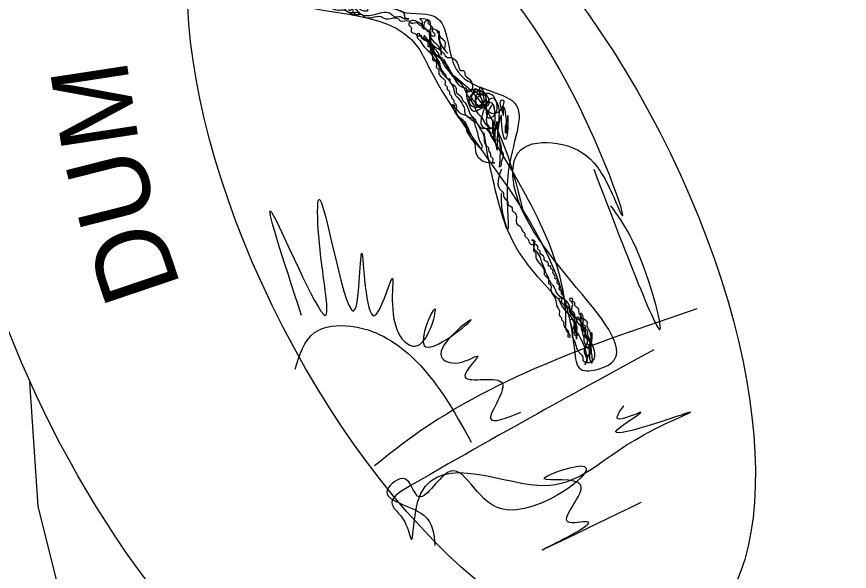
# Model space of a CAD drawing. Extents: x 160093 to 164626, y 177093 to 182727.
# Drawn here: x 162728.73 to 162751.34, y 178249.07 to 178264.12 of the extents above; entities that cross this region are included whole.
import ezdxf

# ---------------------------------------------------------------- set-up
doc = ezdxf.new("R2010")
doc.units = 0
doc.layers.add('Level 38', color=7, linetype='Continuous')
doc.layers.add('Level 40', color=7, linetype='Continuous')

msp = doc.modelspace()

# ---------------------------------------------------------------- linework, layer by layer
at = {"layer": 'Level 38'}
msp.add_lwpolyline([(162729.077, 178254.203), (162729.302, 178250.833), (162730.119, 178247.567), (162730.772, 178245.77), (162730.772, 178245.443)], dxfattribs=at)
for centre, major_axis, ratio in [((162741.339, 178258.256), (9.304, -16.888), 0.662421), ((162741.077, 178258.344), (5.775, -11.2), 0.456916)]:
    msp.add_ellipse(centre, major_axis=major_axis, ratio=ratio, dxfattribs=at)
for points in [[(162733.843, 178267.269), (162735.477, 178264.761), (162739.619, 178263.302), (162739.91, 178262.777), (162743.877, 178255.077), (162744.052, 178254.552), (162744.519, 178254.552), (162742.244, 178259.511), (162742.419, 178260.502), (162743.41, 178260.677), (162744.402, 178260.152), (162745.044, 178258.986), (162739.619, 178266.277), (162739.093, 178266.277), (162738.102, 178268.552), (162736.818, 178267.736), (162738.102, 178265.927), (162736.935, 178264.936), (162736.468, 178264.936), (162735.01, 178265.752), (162733.843, 178267.911)], [(162738.802, 178265.286), (162739.093, 178264.294), (162740.085, 178264.119), (162740.727, 178262.602), (162742.244, 178261.786), (162742.069, 178259.802), (162742.069, 178258.344), (162741.602, 178259.977), (162741.427, 178260.969)], [(162737.052, 178264.352), (162737.168, 178264.352), (162737.227, 178264.352), (162737.46, 178264.294), (162737.635, 178264.294), (162737.752, 178264.236), (162737.985, 178264.236), (162738.102, 178264.177), (162738.452, 178264.177), (162738.918, 178264.177), (162738.977, 178264.119), (162739.152, 178264.119), (162739.268, 178264.061), (162739.385, 178264.061), (162739.327, 178264.061), (162739.268, 178264.119), (162739.268, 178264.177), (162739.093, 178264.294), (162738.918, 178264.352), (162738.743, 178264.469), (162738.568, 178264.527), (162738.102, 178264.644), (162738.16, 178264.644), (162738.393, 178264.411), (162738.452, 178264.411), (162738.452, 178264.469), (162738.51, 178264.644), (162738.743, 178264.411), (162738.685, 178264.469), (162738.685, 178264.586), (162738.627, 178264.586), (162738.627, 178264.527), (162738.627, 178264.411), (162738.277, 178264.644), (162738.102, 178264.644), (162737.927, 178264.586), (162737.927, 178264.527), (162737.985, 178264.469), (162738.16, 178264.352), (162738.218, 178264.352), (162738.16, 178264.411), (162738.16, 178264.469), (162738.043, 178264.586), (162737.985, 178264.586), (162737.927, 178264.527), (162737.985, 178264.411), (162738.102, 178264.294), (162738.277, 178264.294), (162738.218, 178264.352), (162737.868, 178264.352), (162737.868, 178264.236), (162738.043, 178264.177), (162737.868, 178264.352), (162737.752, 178264.352), (162737.752, 178264.294), (162737.81, 178264.294), (162737.81, 178264.411), (162737.752, 178264.469), (162737.693, 178264.469), (162737.635, 178264.527), (162737.635, 178264.469), (162737.577, 178264.469), (162737.635, 178264.411), (162737.635, 178264.352), (162737.752, 178264.236), (162737.868, 178264.177), (162737.985, 178264.177), (162738.102, 178264.177), (162738.16, 178264.119), (162738.627, 178264.119), (162738.743, 178264.061), (162739.093, 178264.061), (162739.152, 178264.002), (162739.385, 178264.002), (162739.444, 178263.944), (162739.619, 178263.944), (162739.677, 178263.886), (162739.735, 178263.886), (162739.735, 178263.827), (162739.794, 178263.827), (162739.91, 178263.711), (162739.969, 178263.711), (162739.969, 178263.652), (162740.027, 178263.594), (162740.085, 178263.594), (162740.085, 178263.652), (162740.027, 178263.711), (162740.027, 178263.827), (162739.969, 178263.886), (162739.969, 178263.944), (162739.735, 178264.061), (162739.677, 178264.061), (162739.735, 178264.002), (162739.735, 178263.886), (162739.852, 178263.769), (162739.969, 178263.769), (162739.969, 178263.886)], [(162739.969, 178263.886), (162739.91, 178263.944), (162739.91, 178264.002), (162739.852, 178264.002), (162739.794, 178263.944), (162739.794, 178263.769), (162739.794, 178263.827), (162739.677, 178263.944), (162739.56, 178264.002), (162739.444, 178264.002), (162739.385, 178263.944), (162739.385, 178263.886), (162739.444, 178263.827), (162739.444, 178263.711), (162739.56, 178263.652), (162739.619, 178263.594), (162739.677, 178263.594), (162739.735, 178263.536), (162739.969, 178263.419), (162740.027, 178263.361), (162740.319, 178263.127), (162740.435, 178263.011), (162740.494, 178263.011), (162740.727, 178262.777), (162740.785, 178262.661), (162740.844, 178262.661), (162740.902, 178262.602), (162740.902, 178262.544), (162741.019, 178262.427), (162741.019, 178262.077), (162740.96, 178262.077), (162740.96, 178262.136), (162740.844, 178262.194), (162740.669, 178262.369), (162740.435, 178262.719), (162740.377, 178262.836), (162740.26, 178262.952), (162740.144, 178263.186), (162740.085, 178263.244), (162740.027, 178263.361), (162739.969, 178263.419), (162739.969, 178263.652), (162739.969, 178263.594), (162740.027, 178263.477), (162740.26, 178263.127), (162740.26, 178263.069), (162740.26, 178263.244), (162740.202, 178263.652), (162740.202, 178263.711), (162740.144, 178263.711), (162740.202, 178263.652), (162740.202, 178263.594), (162740.26, 178263.361), (162740.377, 178263.186), (162740.435, 178263.127), (162740.377, 178263.186), (162740.377, 178263.419), (162740.26, 178263.536), (162740.202, 178263.652), (162740.085, 178263.769), (162739.969, 178263.769), (162739.969, 178263.477), (162740.027, 178263.186), (162740.202, 178262.836), (162740.144, 178262.894), (162740.144, 178263.011), (162740.027, 178263.244), (162739.969, 178263.419), (162739.91, 178263.477), (162739.852, 178263.536), (162739.91, 178263.477), (162740.027, 178263.302), (162740.085, 178263.127), (162740.26, 178263.011), (162740.319, 178262.952), (162740.61, 178262.486), (162740.785, 178262.311), (162740.902, 178262.136), (162741.019, 178261.902), (162741.135, 178261.727), (162741.252, 178261.494), (162741.369, 178261.377), (162741.427, 178261.261), (162741.544, 178261.086), (162741.602, 178260.969), (162741.66, 178260.969), (162741.66, 178261.027), (162741.719, 178261.261), (162741.719, 178261.436), (162741.602, 178261.786), (162741.544, 178261.786), (162741.485, 178261.727), (162741.369, 178261.436), (162741.369, 178261.144), (162741.485, 178261.086), (162741.602, 178261.086), (162741.719, 178261.202)], [(162741.835, 178260.036), (162741.894, 178260.094), (162741.894, 178260.152), (162741.952, 178260.386), (162741.894, 178260.502), (162741.894, 178260.561), (162741.835, 178260.736), (162741.719, 178260.794), (162741.427, 178261.086), (162741.369, 178261.086), (162741.252, 178261.202), (162741.077, 178261.319), (162741.019, 178261.377), (162740.785, 178261.494), (162740.61, 178261.669), (162740.552, 178261.727), (162740.61, 178261.727), (162740.61, 178261.669), (162740.844, 178261.319), (162741.135, 178260.794), (162741.369, 178260.561), (162741.369, 178260.619), (162741.31, 178260.736), (162741.252, 178260.969), (162741.194, 178261.144), (162741.077, 178261.377), (162741.019, 178261.377), (162740.902, 178261.552), (162740.902, 178261.611), (162740.844, 178261.727), (162740.785, 178261.844), (162740.669, 178261.961), (162740.61, 178262.136), (162740.494, 178262.369), (162740.377, 178262.486), (162740.202, 178262.777), (162740.027, 178263.127), (162739.969, 178263.186), (162739.969, 178263.302), (162739.91, 178263.302), (162739.91, 178263.361), (162739.852, 178263.477), (162739.794, 178263.477), (162739.794, 178263.536), (162739.735, 178263.536), (162739.735, 178263.594), (162739.677, 178263.594), (162739.677, 178263.652), (162739.619, 178263.652), (162739.619, 178263.536), (162739.677, 178263.477), (162739.794, 178263.302), (162739.91, 178263.186), (162739.969, 178263.127), (162740.027, 178263.011), (162740.027, 178262.952), (162740.144, 178262.894), (162740.202, 178262.836), (162740.319, 178262.602), (162740.377, 178262.544), (162740.435, 178262.427), (162740.494, 178262.427), (162740.494, 178262.369), (162740.61, 178262.252), (162740.669, 178262.136), (162740.669, 178262.077), (162740.785, 178261.961), (162740.844, 178261.844), (162740.902, 178261.786), (162741.077, 178261.436), (162741.135, 178261.377), (162741.31, 178261.086), (162741.427, 178260.852), (162741.427, 178260.736), (162741.485, 178260.619), (162741.544, 178260.561), (162741.544, 178260.502), (162741.602, 178260.386), (162741.602, 178260.327), (162741.66, 178260.269), (162741.66, 178260.152), (162741.719, 178260.152), (162741.602, 178260.152), (162741.194, 178260.561), (162741.194, 178260.619), (162741.135, 178260.736), (162741.019, 178260.911), (162740.96, 178261.027), (162740.96, 178261.086), (162740.902, 178261.202), (162740.844, 178261.261), (162740.669, 178261.611), (162740.669, 178261.727), (162740.61, 178261.786), (162740.61, 178261.844), (162740.552, 178261.902), (162740.552, 178261.961)], [(162740.552, 178261.961), (162740.494, 178262.019), (162740.494, 178262.077), (162740.435, 178262.136), (162740.435, 178262.194), (162740.377, 178262.252), (162740.377, 178262.369), (162740.319, 178262.427), (162740.26, 178262.486), (162740.202, 178262.602), (162740.202, 178262.661), (162740.144, 178262.719), (162740.144, 178262.836), (162740.027, 178263.069), (162740.027, 178263.127), (162739.91, 178263.419), (162739.852, 178263.477), (162739.852, 178263.536), (162739.794, 178263.594), (162739.794, 178263.536), (162739.91, 178263.419), (162739.969, 178263.244), (162740.26, 178262.952), (162740.319, 178262.836), (162740.785, 178262.369), (162742.477, 178258.869)], [(162741.719, 178261.202), (162741.66, 178261.727), (162741.485, 178261.319), (162741.544, 178261.144), (162741.66, 178261.086), (162741.777, 178261.144), (162741.835, 178261.377), (162741.835, 178261.611), (162741.777, 178261.786), (162741.66, 178261.902), (162741.544, 178261.844), (162741.485, 178261.669), (162741.485, 178261.494), (162741.544, 178261.377), (162741.602, 178261.377), (162741.777, 178261.611), (162741.719, 178261.902), (162741.602, 178262.019), (162741.427, 178262.019), (162741.194, 178261.844), (162741.194, 178261.727), (162741.485, 178261.902), (162741.369, 178262.077), (162741.31, 178262.077), (162741.194, 178262.136), (162741.135, 178262.077), (162741.077, 178261.961), (162741.077, 178261.844), (162741.135, 178261.727), (162741.194, 178261.669), (162741.369, 178261.727), (162741.427, 178261.902), (162741.369, 178262.019), (162741.194, 178261.961), (162741.194, 178261.844), (162741.252, 178261.669), (162741.369, 178261.669), (162741.485, 178261.786), (162741.427, 178262.019), (162741.252, 178262.136), (162741.135, 178262.136), (162741.135, 178262.077), (162741.077, 178261.961), (162741.135, 178261.844), (162741.252, 178261.727), (162741.427, 178261.669), (162741.544, 178261.727), (162741.544, 178261.902), (162741.369, 178262.077), (162741.019, 178261.902), (162741.019, 178261.786), (162741.135, 178261.669), (162741.252, 178261.669), (162741.369, 178261.786), (162741.369, 178261.844), (162741.194, 178262.077), (162741.019, 178262.136), (162740.96, 178262.077), (162740.96, 178261.902), (162741.019, 178261.727), (162741.135, 178261.552), (162741.31, 178261.611), (162741.485, 178261.727), (162741.31, 178262.194), (162741.31, 178262.019), (162741.369, 178261.844), (162741.485, 178261.611), (162741.66, 178261.494), (162741.835, 178261.552), (162741.952, 178261.727), (162741.952, 178261.844), (162741.894, 178261.844), (162741.894, 178261.611), (162741.952, 178261.436), (162741.952, 178261.669), (162742.01, 178261.436), (162742.01, 178260.969), (162742.01, 178261.144), (162742.069, 178261.377), (162742.069, 178261.436), (162742.069, 178261.377), (162742.069, 178261.319), (162742.069, 178261.086), (162742.01, 178260.794), (162741.894, 178261.377), (162741.894, 178261.436), (162741.835, 178261.261), (162741.777, 178260.502), (162741.719, 178260.852), (162741.66, 178261.319), (162741.66, 178261.086), (162741.719, 178260.736), (162741.719, 178260.794), (162741.777, 178261.261), (162741.777, 178261.144), (162741.835, 178260.794), (162741.835, 178260.036)], [(162743.527, 178255.952), (162743.527, 178255.894), (162743.585, 178255.836), (162743.585, 178255.777), (162743.644, 178255.661), (162743.702, 178255.602), (162743.702, 178255.486), (162743.702, 178255.427), (162743.76, 178255.427), (162743.702, 178255.544), (162743.644, 178255.777), (162741.602, 178260.911)], [(162741.894, 178259.977), (162741.894, 178259.394), (162741.952, 178259.336), (162741.952, 178259.277), (162742.01, 178259.161), (162742.069, 178259.102), (162742.069, 178259.044), (162742.185, 178258.927), (162742.185, 178258.869), (162742.244, 178258.811), (162742.302, 178258.694), (162742.302, 178258.519), (162742.419, 178258.402), (162742.477, 178258.286), (162742.535, 178258.227), (162742.535, 178258.169), (162742.594, 178258.111), (162742.652, 178257.994), (162742.71, 178257.936), (162742.769, 178257.936), (162742.769, 178257.819), (162742.769, 178257.761), (162742.827, 178257.702), (162742.827, 178257.644), (162743.06, 178257.177), (162743.06, 178257.119), (162743.119, 178257.061), (162743.235, 178256.886), (162743.294, 178256.827), (162743.41, 178256.594), (162743.644, 178256.361), (162743.644, 178256.302), (162743.702, 178256.244), (162743.76, 178256.127), (162743.877, 178256.011), (162743.994, 178255.777), (162744.11, 178255.661), (162744.11, 178255.602), (162744.169, 178255.544), (162744.169, 178255.427), (162744.227, 178255.427), (162744.227, 178255.252), (162744.285, 178255.194), (162744.285, 178254.961), (162744.227, 178254.902), (162744.227, 178254.844), (162744.169, 178254.961), (162744.169, 178255.136), (162744.227, 178255.369), (162744.169, 178255.427), (162744.169, 178255.661), (162744.11, 178255.719), (162744.11, 178255.777), (162744.052, 178255.836), (162743.994, 178255.952), (162743.935, 178255.952), (162743.935, 178255.894), (162743.877, 178255.777), (162743.877, 178255.602), (162743.935, 178255.486), (162743.935, 178255.369), (162743.935, 178255.427), (162743.877, 178255.486), (162743.877, 178255.602), (162743.877, 178255.777), (162743.76, 178256.011), (162743.469, 178256.419), (162743.469, 178256.477), (162743.527, 178256.477), (162743.527, 178256.419), (162743.585, 178256.302), (162743.702, 178256.244), (162743.76, 178256.069), (162743.819, 178256.011), (162743.877, 178255.894), (162743.877, 178255.836), (162743.935, 178255.719), (162743.935, 178255.602), (162743.935, 178255.486), (162743.994, 178255.486), (162743.935, 178255.544), (162743.935, 178255.777), (162743.877, 178255.894), (162743.877, 178256.069), (162743.819, 178256.127), (162743.819, 178256.361), (162743.76, 178256.419), (162743.76, 178256.477), (162743.819, 178256.477), (162743.819, 178256.419), (162743.877, 178256.361), (162743.877, 178256.302), (162743.935, 178256.244), (162743.994, 178256.127), (162743.994, 178256.069), (162744.052, 178256.011), (162744.052, 178255.952)], [(162744.402, 178259.977), (162746.21, 178255.719), (162745.394, 178258.169), (162744.869, 178258.986)], [(162736.468, 178256.011), (162735.652, 178258.811), (162737.11, 178256.011), (162736.935, 178258.169), (162736.935, 178259.161), (162737.927, 178256.186), (162738.102, 178257.702), (162738.452, 178256.011), (162738.918, 178257.002), (162739.093, 178255.544), (162739.619, 178255.194), (162740.085, 178256.186), (162739.794, 178255.194), (162741.077, 178255.894), (162740.26, 178254.902), (162740.727, 178254.727), (162741.252, 178254.902), (162740.902, 178254.377), (162741.894, 178254.202), (162741.602, 178253.211), (162742.419, 178253.386)], [(162743.702, 178256.186), (162741.894, 178259.161), (162741.894, 178259.336)], [(162744.052, 178255.952), (162744.11, 178255.894), (162744.11, 178255.777), (162744.169, 178255.719), (162744.169, 178255.661), (162744.227, 178255.602), (162744.227, 178255.544), (162744.285, 178255.369), (162744.285, 178254.727), (162744.227, 178254.727), (162744.227, 178254.786), (162744.227, 178254.844), (162743.994, 178255.486), (162743.935, 178255.602), (162743.819, 178255.894), (162743.76, 178255.894), (162743.76, 178255.836), (162743.819, 178255.602), (162743.819, 178255.427), (162743.877, 178255.311), (162743.935, 178255.136), (162743.994, 178255.019), (162744.052, 178254.961), (162744.11, 178254.844), (162744.11, 178254.786), (162744.169, 178254.727), (162744.169, 178254.669), (162744.227, 178254.844), (162744.285, 178254.961), (162744.285, 178255.194), (162744.344, 178255.369), (162744.344, 178255.544), (162744.344, 178255.311), (162744.285, 178255.136), (162744.285, 178255.019), (162744.285, 178255.602), (162744.227, 178255.719), (162744.227, 178255.836), (162744.11, 178255.952), (162744.11, 178256.011), (162744.052, 178256.069), (162744.052, 178255.894), (162744.052, 178255.719), (162744.11, 178255.486), (162744.227, 178255.136), (162744.285, 178255.077), (162744.285, 178254.844), (162744.344, 178254.727), (162744.344, 178255.019), (162744.285, 178255.311), (162744.169, 178255.544), (162744.11, 178255.719), (162743.994, 178255.894), (162743.877, 178255.952), (162743.644, 178256.419), (162743.585, 178256.477), (162743.585, 178256.536), (162743.527, 178256.594), (162743.527, 178256.652), (162743.469, 178256.711), (162743.469, 178256.827), (162743.41, 178256.886), (162743.41, 178256.944), (162743.41, 178257.002), (162743.352, 178257.002), (162743.352, 178257.061), (162743.294, 178257.177), (162743.294, 178257.236), (162743.235, 178257.294), (162743.235, 178257.352), (162743.177, 178257.352), (162743.177, 178257.411), (162743.06, 178257.527), (162743.06, 178257.586), (162742.944, 178257.702), (162742.944, 178257.761), (162742.885, 178257.819), (162742.885, 178257.877), (162742.769, 178257.994), (162742.769, 178258.052), (162742.71, 178258.052), (162742.769, 178258.052), (162742.769, 178257.877), (162742.827, 178257.761), (162742.944, 178257.586), (162743.002, 178257.411), (162743.06, 178257.294), (162743.119, 178257.119), (162743.177, 178257.002), (162743.177, 178256.886), (162743.235, 178256.827), (162743.235, 178256.711), (162743.352, 178256.477), (162743.41, 178256.244), (162743.469, 178256.127), (162743.469, 178256.011), (162743.527, 178255.952)], [(162747.202, 178256.186), (162739.268, 178252.569), (162738.452, 178251.927)], [(162736.293, 178254.552), (162736.818, 178255.544), (162737.81, 178255.719), (162739.444, 178254.902), (162741.077, 178252.569)], [(162746.035, 178255.077), (162739.444, 178251.402), (162738.918, 178250.936), (162739.268, 178250.411), (162739.444, 178249.944), (162739.619, 178250.936), (162742.885, 178251.402), (162746.035, 178252.919), (162747.027, 178253.386), (162745.044, 178252.919), (162745.685, 178253.386), (162745.044, 178253.211), (162745.219, 178253.561)], [(162745.685, 178250.936), (162743.235, 178249.769), (162744.227, 178250.411), (162743.702, 178250.411), (162744.052, 178251.402), (162743.06, 178251.577), (162744.052, 178251.927), (162741.894, 178250.761), (162740.435, 178251.752), (162739.619, 178251.111), (162739.268, 178251.577), (162738.802, 178251.286), (162739.794, 178250.586), (162740.085, 178249.769)]]:
    msp.add_spline(points, degree=3, dxfattribs=at)

# ---------------------------------------------------------------- texts
at = {"layer": 'Level 40'}
for s, rotation, p in [('M', 98.6916, (162732.054, 178260.702)), ('U', 104.2269, (162732.557, 178258.713)), ('D', 108.6922, (162733.203, 178256.801))]:
    msp.add_text(s, height=2.1, rotation=rotation, dxfattribs=at).set_placement(p)

doc.saveas('drawing.dxf')
